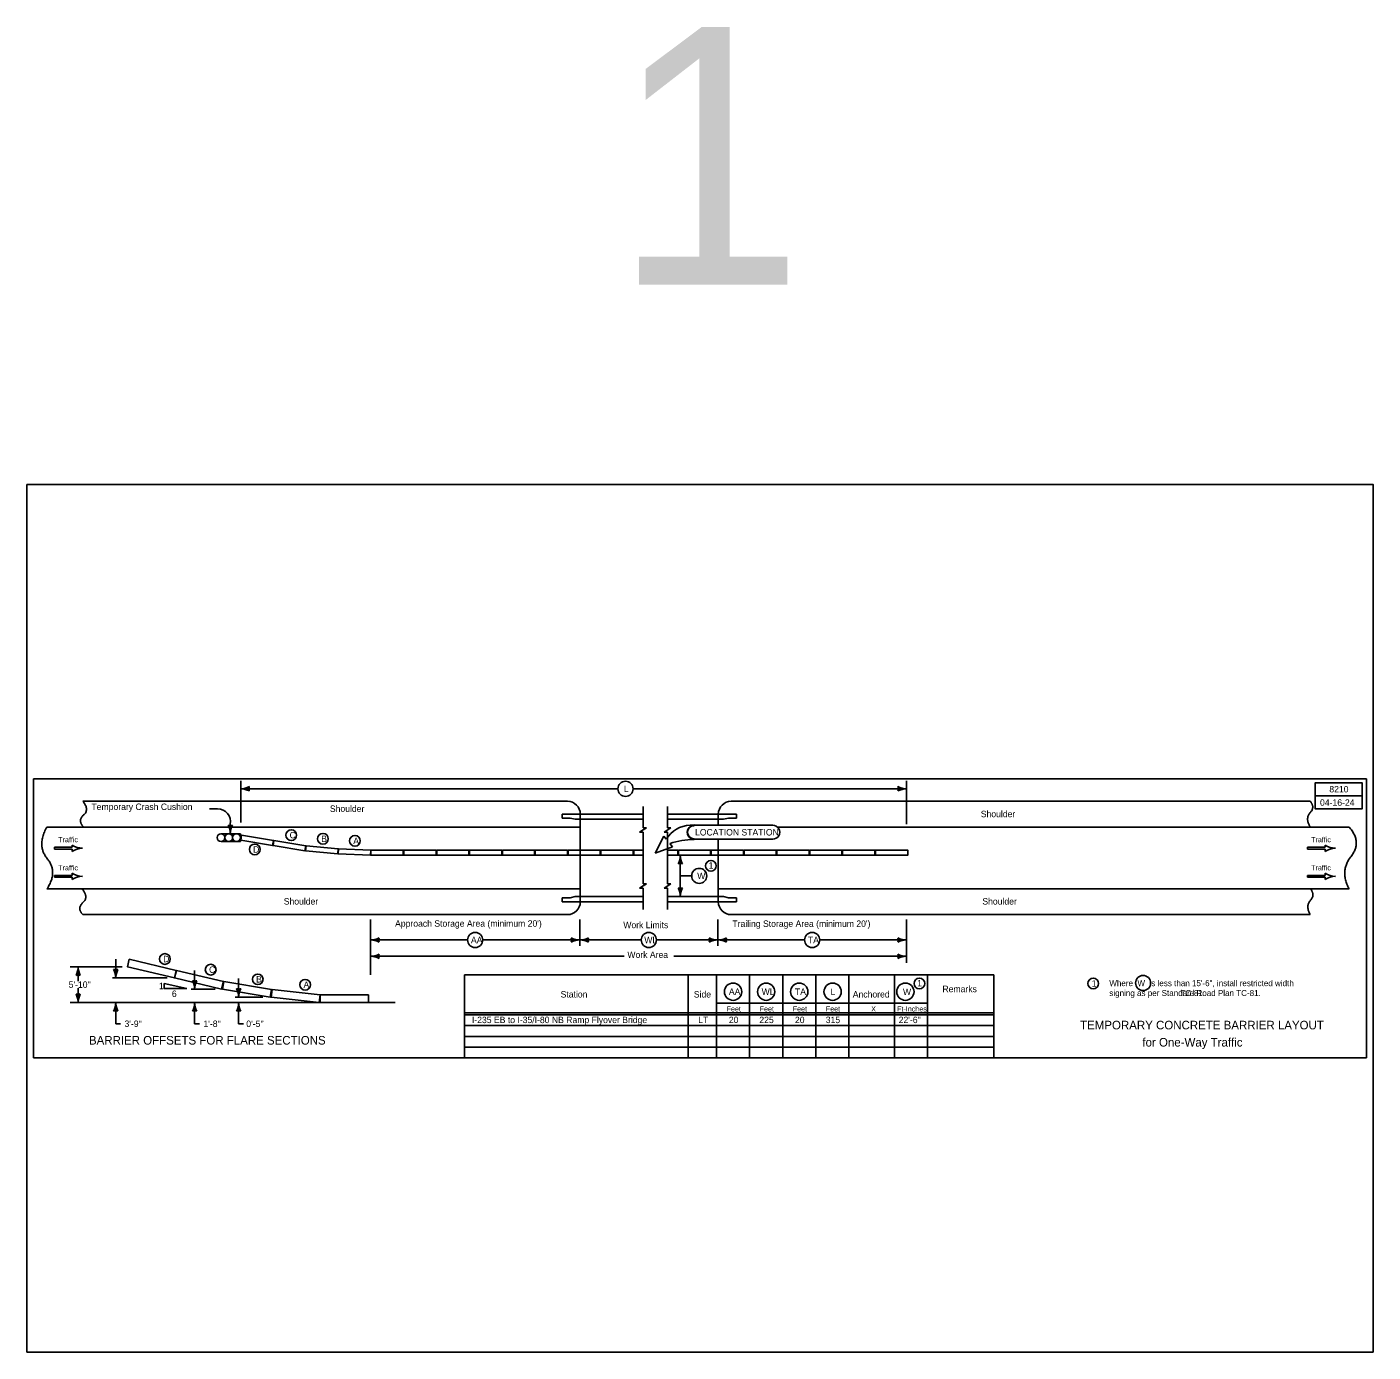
# Model space of a CAD drawing. Extents: x 10133 to 81668, y 7924 to 11018.
# Drawn here: x 10133 to 13268, y 7924 to 11009 of the extents above; entities that cross this region are included whole.
import ezdxf

# ---------------------------------------------------------------- set-up
doc = ezdxf.new("R2010")
doc.units = 0
for name, color, linetype in [('dsnCellsNorthArrow', 7, 'Continuous'), ('DsnShtRevisedText', 7, 'Continuous'), ('dsnTextTabulation', 7, 'Continuous'), ('Level 12', 7, 'Continuous'), ('Level 6', 7, 'Continuous'), ('Level 7', 7, 'Continuous'), ('Level 8', 7, 'Continuous'), ('SheetAddendum', 7, 'Continuous'), ('SheetBorder', 7, 'Continuous'), ('SheetText', 7, 'Continuous'), ('ShtPlotIdentification', 7, 'Continuous')]:
    doc.layers.add(name, color=color, linetype=linetype)

msp = doc.modelspace()

# ---------------------------------------------------------------- linework, layer by layer
at = {"layer": 'dsnCellsNorthArrow'}
for p, q in [((10505.1, 8770.1), (10452.5, 8782.5)), ((10452.5, 8782.5), (10452.5, 8770.1)), ((10452.5, 8770.1), (10505.1, 8770.1))]:
    msp.add_line(p, q, dxfattribs=at)
at = {"layer": 'DsnShtRevisedText'}
msp.add_line((10147.5, 9259), (10147.5, 9259), dxfattribs=at)
at = {"layer": 'dsnTextTabulation'}
for p, q in [((10630.5, 9254.1), (10630.5, 9156.6)), ((12181, 9254.1), (12181, 9153.2)), ((10630.5, 9235.4), (11509, 9235.4)), ((11544.3, 9235.4), (12181, 9235.4)), ((10262.8, 9206.4), (11391.3, 9206.4)), ((10576.7, 9188.7), (10557.9, 9188.7)), ((11567.3, 9194.4), (11567.3, 9144.6)), ((11624.4, 9194.4), (11624.4, 9144.6)), ((11772.7, 9206.4), (13121.1, 9206.4)), ((11421.3, 9176.4), (11379.3, 9176.4)), ((11379.3, 9176.4), (11379.3, 9167.4)), ((11379.3, 9167.4), (11397.3, 9167.4)), ((11409.3, 9164.4), (11397.3, 9167.4)), ((11421.3, 9164.4), (11409.3, 9164.4)), ((11421.3, 9176.4), (11421.3, 8972.4)), ((11421.3, 9176.4), (11567.3, 9176.4)), ((11421.3, 9164.4), (11567.3, 9164.4)), ((11624.4, 9176.4), (11742.7, 9176.4)), ((11624.4, 9164.4), (11742.7, 9164.4)), ((11742.7, 9176.4), (11784.7, 9176.4)), ((11742.7, 9176.4), (11742.7, 9150.5)), ((11742.7, 9164.4), (11754.7, 9164.4)), ((11754.7, 9164.4), (11766.7, 9167.4)), ((11784.7, 9167.4), (11766.7, 9167.4)), ((11784.7, 9176.4), (11784.7, 9167.4)), ((10179.2, 9146.4), (11421.3, 9146.4)), ((10584.6, 9130.9), (10629.6, 9130.9)), ((10606.2, 9153.4), (10606.2, 9130.9)), ((10629.6, 9130.9), (10629.6, 9112.8)), ((11559.3, 9134.5), (11567.3, 9139.5)), ((11559.3, 9134.5), (11567.3, 9134.5)), ((11567.3, 9139.5), (11575.3, 9144.6)), ((11575.3, 9144.6), (11567.3, 9144.6)), ((11567.3, 9134.5), (11567.3, 9074.4)), ((11595.8, 9085.5), (11615.9, 9125.5)), ((11615.9, 9125.5), (11621.6, 9118.4)), ((11616.4, 9134.5), (11632.4, 9144.6)), ((11616.4, 9134.5), (11624.4, 9134.5)), ((11632.4, 9144.6), (11624.4, 9144.6)), ((11624.4, 9134.5), (11624.4, 9074.4)), ((11676.8, 9151), (11686.3, 9151.4)), ((11686.3, 9151.4), (11686.3, 9149.6)), ((11686.3, 9150.5), (11869.4, 9150.5)), ((11880.2, 9146.4), (13211.5, 9146.4)), ((10238.1, 9099.3), (10196.8, 9099.3)), ((10196.8, 9099.3), (10196.8, 9094.8)), ((10196.8, 9094.8), (10238.1, 9094.8)), ((10238.1, 9104.5), (10238.1, 9099.3)), ((10238.1, 9094.8), (10238.1, 9089.5)), ((10262, 9097), (10262, 9097)), ((10629.6, 9112.8), (10584.6, 9112.8)), ((10628.4, 9118.6), (10629.7, 9118.3)), ((10630.1, 9114.9), (10630.1, 9114.9)), ((11636, 9100.5), (11595.8, 9085.5)), ((11630.1, 9107.8), (11636, 9100.5)), ((11686.3, 9118.9), (11686.3, 9117.1)), ((11686.3, 9118), (11869.4, 9118)), ((11742.7, 9118), (11742.7, 8972.4)), ((13155.8, 9099.3), (13114.6, 9099.3)), ((13114.6, 9099.3), (13114.6, 9094.8)), ((13114.6, 9094.8), (13155.8, 9094.8)), ((13155.8, 9104.5), (13155.8, 9099.3)), ((13155.8, 9094.8), (13155.8, 9089.5)), ((13179.8, 9097), (13179.8, 9097)), ((11567.3, 9074.4), (11567.3, 9014.4)), ((11624.4, 9074.4), (11624.4, 9014.4)), ((11654, 9080.7), (11654, 8984.4)), ((10238.1, 9033.8), (10196.8, 9033.8)), ((10196.8, 9033.8), (10196.8, 9029.3)), ((10196.8, 9029.3), (10238.1, 9029.3)), ((10238.1, 9039.1), (10238.1, 9033.8)), ((10238.1, 9029.3), (10238.1, 9024.1)), ((10262, 9031.6), (10262, 9031.6)), ((11680.6, 9032.6), (11654, 9032.6)), ((13155.8, 9033.8), (13114.6, 9033.8)), ((13114.6, 9033.8), (13114.6, 9029.3)), ((13114.6, 9029.3), (13155.8, 9029.3)), ((13155.8, 9039.1), (13155.8, 9033.8)), ((13155.8, 9029.3), (13155.8, 9024.1)), ((13179.8, 9031.6), (13179.8, 9031.6)), ((10179.2, 9002.4), (11421.3, 9002.4)), ((11559.3, 9004.3), (11567.3, 9009.3)), ((11559.3, 9004.3), (11567.3, 9004.3)), ((11567.3, 9009.3), (11575.3, 9014.4)), ((11575.3, 9014.4), (11567.3, 9014.4)), ((11567.3, 9004.3), (11567.3, 8954.4)), ((11616.4, 9004.3), (11632.4, 9014.4)), ((11616.4, 9004.3), (11624.4, 9004.3)), ((11632.4, 9014.4), (11624.4, 9014.4)), ((11624.4, 9004.3), (11624.4, 8954.4)), ((11742.7, 9002.4), (13211.5, 9002.4)), ((11379.3, 8981.4), (11397.3, 8981.4)), ((11379.3, 8972.4), (11379.3, 8981.4)), ((11421.3, 8972.4), (11379.3, 8972.4)), ((11409.3, 8984.4), (11397.3, 8981.4)), ((11421.3, 8984.4), (11409.3, 8984.4)), ((11421.3, 8984.4), (11567.3, 8984.4)), ((11421.3, 8972.4), (11567.3, 8972.4)), ((11624.4, 8984.4), (11742.7, 8984.4)), ((11624.4, 8972.4), (11742.7, 8972.4)), ((11742.7, 8984.4), (11754.7, 8984.4)), ((11742.7, 8972.4), (11784.7, 8972.4)), ((11754.7, 8984.4), (11766.7, 8981.4)), ((11784.7, 8981.4), (11766.7, 8981.4)), ((11784.7, 8972.4), (11784.7, 8981.4)), ((10262.8, 8942.4), (11391.3, 8942.4)), ((11772.7, 8942.4), (13121.1, 8942.4)), ((10932.6, 8931.2), (10932.6, 8802)), ((11420.1, 8931.2), (11420.1, 8869.9)), ((11741.5, 8931.2), (11741.5, 8869.9)), ((12181, 8931.2), (12181, 8830.3)), ((10932.6, 8883.4), (11158.7, 8883.4)), ((11194, 8883.4), (11420.1, 8883.4)), ((11420.1, 8883.4), (11563.3, 8883.4)), ((11598.3, 8883.4), (11741.5, 8883.4)), ((11611, 8883.4), (11741.5, 8883.4)), ((11741.5, 8883.4), (11943.6, 8883.4)), ((11978.9, 8883.4), (12181, 8883.4)), ((10932.6, 8845.5), (11523.4, 8845.5)), ((11638.7, 8845.5), (12181, 8845.5)), ((11640.1, 8845.5), (11741.5, 8845.5)), ((10354.1, 8821), (10232.9, 8821)), ((10251.9, 8821), (10251.9, 8787.5)), ((10339.5, 8838.5), (10339.5, 8795)), ((10523.1, 8812.1), (10523.1, 8768.6)), ((10459, 8795), (10331.8, 8795)), ((10625.5, 8793.5), (10625.5, 8750.1)), ((11672.6, 8609), (11672.6, 8802)), ((11738.6, 8609), (11738.6, 8802)), ((11815.6, 8609), (11815.6, 8802)), ((11892.6, 8609), (11892.6, 8802)), ((11969.6, 8609), (11969.6, 8802)), ((10251.9, 8771.2), (10251.9, 8737.7)), ((10570.9, 8768.6), (10515.3, 8768.6)), ((10681.8, 8750.1), (10617.7, 8750.1)), ((10990.3, 8737.7), (10232.9, 8737.7)), ((10339.5, 8737.7), (10339.5, 8688.4)), ((10523.1, 8737.7), (10523.1, 8688.4)), ((10625.5, 8737.7), (10625.5, 8710.8)), ((11738.6, 8736.2), (12230.1, 8736.2)), ((10339.5, 8688.4), (10350.7, 8688.4)), ((10523.1, 8688.4), (10534.2, 8688.4)), ((10625.5, 8710.8), (10625.5, 8688.4)), ((10625.5, 8688.4), (10636.6, 8688.4)), ((11151.2, 8714), (12384.1, 8714)), ((11151.2, 8709), (12384.1, 8709))]:
    msp.add_line(p, q, dxfattribs=at)
for points in [[(10706.4, 9115.3), (10632.4, 9127.4), (10630.5, 9115.6), (10704.5, 9103.4)], [(10781.9, 9102.9), (10707.9, 9115), (10705.9, 9103.2), (10780, 9091)], [(10857.3, 9095.7), (10782.6, 9102.8), (10781.5, 9090.8), (10856.2, 9083.7)], [(10933.1, 9092.7), (10858.1, 9095.7), (10857.7, 9083.7), (10932.6, 9080.7)], [(10933.8, 9092.7), (11008.8, 9092.7), (11008.8, 9080.7), (10933.8, 9080.7)], [(11010.3, 9092.7), (11085.3, 9092.7), (11085.3, 9080.7), (11010.3, 9080.7)], [(11086.8, 9092.7), (11161.8, 9092.7), (11161.8, 9080.7), (11086.8, 9080.7)], [(11163.3, 9092.7), (11238.3, 9092.7), (11238.3, 9080.7), (11163.3, 9080.7)], [(11239.8, 9092.7), (11314.8, 9092.7), (11314.8, 9080.7), (11239.8, 9080.7)], [(11316.3, 9092.7), (11391.3, 9092.7), (11391.3, 9080.7), (11316.3, 9080.7)], [(11392.8, 9092.7), (11467.8, 9092.7), (11467.8, 9080.7), (11392.8, 9080.7)], [(11469.3, 9092.7), (11544.3, 9092.7), (11544.3, 9080.7), (11469.3, 9080.7)], [(11649.7, 9092.7), (11724.7, 9092.7), (11724.7, 9080.7), (11649.7, 9080.7)], [(11726.2, 9092.7), (11801.2, 9092.7), (11801.2, 9080.7), (11726.2, 9080.7)], [(11802.7, 9092.7), (11877.7, 9092.7), (11877.7, 9080.7), (11802.7, 9080.7)], [(11879.2, 9092.7), (11954.2, 9092.7), (11954.2, 9080.7), (11879.2, 9080.7)], [(11955.7, 9092.7), (12030.7, 9092.7), (12030.7, 9080.7), (11955.7, 9080.7)], [(12032.2, 9092.7), (12107.2, 9092.7), (12107.2, 9080.7), (12032.2, 9080.7)], [(12108.7, 9092.7), (12183.7, 9092.7), (12183.7, 9080.7), (12108.7, 9080.7)], [(10480.3, 8812.6), (10370.9, 8838.5), (10366.7, 8821), (10476.2, 8795.1)], [(10590.1, 8786.6), (10480.6, 8812.5), (10476.5, 8795), (10586, 8769.1)], [(10702.2, 8767.9), (10591.2, 8786.4), (10588.3, 8768.6), (10699.2, 8750.2)], [(10815.3, 8755.6), (10703.5, 8767.9), (10701.5, 8750.1), (10813.3, 8737.7)], [(10927.8, 8755.7), (10815.3, 8755.7), (10815.3, 8737.7), (10927.8, 8737.7)]]:
    msp.add_lwpolyline(points, close=True, dxfattribs=at)
for points in [[(11567.3, 9080.7), (11545.8, 9080.7), (11545.8, 9092.7), (11567.3, 9092.7)], [(11567.3, 9092.7), (11567.3, 9080.7)], [(11624.4, 9080.7), (11624.4, 9092.7)], [(11624.4, 9092.7), (11648.2, 9092.7), (11648.2, 9080.7), (11624.4, 9080.7)]]:
    msp.add_lwpolyline(points, dxfattribs=at)
for centre, radius in [((11526.6, 9235.4), 17.6), ((10584.6, 9121.8), 9), ((10584.6, 9121.8), 9), ((10602.6, 9121.8), 9), ((10602.6, 9121.8), 9), ((10620.6, 9121.8), 9), ((10620.6, 9121.8), 9), ((10748.1, 9127.5), 12.5), ((10821.9, 9119.1), 12.5), ((10896.4, 9114.2), 12.5), ((10663.2, 9094.3), 12.5), ((11725.4, 9056), 12.5), ((11698.3, 9032.6), 17.6), ((11176.4, 8883.4), 17.6), ((11580.8, 8883.4), 17.6), ((11961.2, 8883.4), 17.6), ((10453.8, 8839.2), 12.5), ((10560.5, 8814.3), 12.5), ((10670.2, 8791.9), 12.2), ((10780.5, 8779.2), 12.5), ((11777.1, 8763), 20.1), ((11854.1, 8763), 20.1), ((11931.1, 8763), 20.1), ((12008.9, 8763), 20.1), ((12178.3, 8763), 20.1), ((12211, 8782.2), 12.5), ((12615.8, 8782.2), 12.5), ((12731.9, 8783.3), 17.6)]:
    msp.add_circle(centre, radius, dxfattribs=at)
for centre, radius, start, end in [((10630.5, 9277.9), 42.5, 270, 298.0725), ((10630.5, 9192.9), 42.5, 61.9275, 90), ((10666.1, 9235.4), 16.4, 162.2666, 197.7334), ((12145.4, 9235.4), 16.4, 342.2666, 17.7333), ((12181, 9277.9), 42.5, 241.9275, 270), ((12181, 9192.9), 42.5, 90, 118.0725), ((10576.7, 9158.7), 30, 349.6463, 90), ((11391.3, 9176.4), 30, 0, 90), ((11772.7, 9176.4), 30, 90, 180), ((10606.2, 9166.5), 16.4, 252.2666, 287.7333), ((10563.7, 9130.9), 42.5, 360, 28.0725), ((10648.7, 9130.9), 42.5, 151.9275, 180), ((10264, 9145.3), 48.4, 237.618, 267.648), ((10264, 9048.7), 48.4, 92.352, 122.382), ((13181.7, 9145.3), 48.4, 237.618, 267.648), ((13181.7, 9048.7), 48.4, 92.352, 122.382), ((11611.5, 9080.7), 42.5, 331.9275, 0), ((11654, 9045.1), 16.4, 72.2666, 107.7334), ((11696.5, 9080.7), 42.5, 180, 208.0725), ((10264, 9079.9), 48.4, 237.618, 267.648), ((10264, 8983.3), 48.4, 92.352, 122.382), ((13181.7, 9079.9), 48.4, 237.618, 267.648), ((13181.7, 8983.3), 48.4, 92.352, 122.382), ((11654, 9020.1), 16.4, 252.2666, 287.7334), ((11611.5, 8984.4), 42.5, 0, 28.0725), ((11696.5, 8984.4), 42.5, 151.9275, 180), ((11391.3, 8972.4), 30, 270, 360), ((11772.7, 8972.4), 30, 180, 270), ((10932.6, 8925.9), 42.5, 270, 298.0725), ((10932.6, 8840.9), 42.5, 61.9275, 90), ((10968.2, 8883.4), 16.4, 162.2666, 197.7334), ((11384.5, 8883.4), 16.4, 342.2666, 17.7333), ((11420.1, 8925.9), 42.5, 241.9275, 270), ((11420.1, 8840.9), 42.5, 90, 118.0725), ((11420.1, 8925.9), 42.5, 270, 298.0725), ((11420.1, 8840.9), 42.5, 61.9275, 90), ((11455.7, 8883.4), 16.4, 162.2666, 197.7334), ((11705.9, 8883.4), 16.4, 342.2666, 17.7333), ((11741.5, 8925.9), 42.5, 241.9275, 270), ((11741.5, 8840.9), 42.5, 90, 118.0725), ((11741.5, 8925.9), 42.5, 270, 298.0725), ((11741.5, 8840.9), 42.5, 61.9275, 90), ((11777.1, 8883.4), 16.4, 162.2666, 197.7334), ((12145.4, 8883.4), 16.4, 342.2666, 17.7333), ((12181, 8925.9), 42.5, 241.9275, 270), ((12181, 8840.9), 42.5, 90, 118.0725), ((10932.6, 8888), 42.5, 270, 298.0725), ((10932.6, 8803), 42.5, 61.9275, 90), ((10968.2, 8845.5), 16.4, 162.2666, 197.7334), ((12145.4, 8845.5), 16.4, 342.2666, 17.7333), ((12181, 8888), 42.5, 241.9275, 270), ((12181, 8803), 42.5, 90, 118.0725), ((10209.4, 8821), 42.5, 331.9275, 0), ((10294.4, 8821), 42.5, 180, 208.0725), ((10339.5, 8830.7), 16.4, 252.2666, 287.7334), ((10297, 8795), 42.5, 0, 28.0725), ((10382, 8795), 42.5, 151.9275, 180), ((10251.9, 8785.4), 16.4, 72.2666, 107.7334), ((10523.1, 8804.3), 16.4, 252.2666, 287.7334), ((10480.6, 8768.6), 42.5, 0, 28.0725), ((10565.6, 8768.6), 42.5, 151.9275, 180), ((10251.9, 8773.4), 16.4, 252.2666, 287.7334), ((10209.4, 8737.7), 42.5, 0, 28.0725), ((10294.4, 8737.7), 42.5, 151.9275, 180), ((10625.5, 8785.7), 16.4, 252.2666, 287.7334), ((10583, 8750.1), 42.5, 0, 28.0725), ((10668, 8750.1), 42.5, 151.9275, 180), ((10297, 8737.7), 42.5, 331.9275, 0), ((10339.5, 8702.1), 16.4, 72.2666, 107.7334), ((10382, 8737.7), 42.5, 180, 208.0725), ((10480.6, 8737.7), 42.5, 331.9275, 0), ((10523.1, 8702.1), 16.4, 72.2666, 107.7334), ((10565.6, 8737.7), 42.5, 180, 208.0725), ((10583, 8737.7), 42.5, 331.9275, 0), ((10625.5, 8702.1), 16.4, 72.2666, 107.7334), ((10668, 8737.7), 42.5, 180, 208.0725)]:
    msp.add_arc(centre, radius, start, end, dxfattribs=at)
for centre, major_axis, start_param, end_param in [((11681.3, 9080.7), (-70.8, 0), 4.776871, 5.71778), ((11686.3, 9134.2), (-16.3, 0), 4.712389, 7.853982), ((11686.3, 9134.2), (15.4, 0), 1.570796, 4.712389), ((11869.4, 9134.2), (16.3, 0), 4.712389, 7.853982), ((11683.5, 8961), (-156.9, 0), 4.694293, 5.059134)]:
    msp.add_ellipse(centre, major_axis=major_axis, ratio=0.995025, start_param=start_param, end_param=end_param, dxfattribs=at)
for points in [[(10262.8, 9206.4), (10278.9, 9187.1), (10250, 9161.5), (10264.4, 9146.5)], [(13121.1, 9206.4), (13132.9, 9192.3), (13109.3, 9167.3), (13120.7, 9146.5)], [(10179.2, 9146.4), (10154.6, 9103.8), (10205.3, 9041.6), (10179.2, 9002.4)], [(13211.5, 9146.4), (13242.9, 9112), (13189.5, 9044), (13211.5, 9002.4)], [(10261.2, 9002.4), (10277.3, 8983.1), (10248.4, 8957.5), (10262.8, 8942.4)], [(13121.6, 9002.4), (13133.4, 8988.3), (13109.8, 8963.3), (13121.1, 8942.4)]]:
    msp.add_open_spline(points, degree=2, dxfattribs=at)
at = {"layer": 'Level 12'}
for p, q in [((11151.2, 8802), (11151.2, 8609)), ((11151.2, 8802), (12384.1, 8802)), ((12046.6, 8609), (12046.6, 8802)), ((12153.1, 8609), (12153.1, 8802)), ((12230.1, 8609), (12230.1, 8802)), ((12384.1, 8609), (12384.1, 8802))]:
    msp.add_line(p, q, dxfattribs=at)
at = {"layer": 'Level 8'}
for p, q in [((10147.5, 9259), (13252.5, 9259)), ((10147.5, 8609), (10147.5, 9259)), ((13252.5, 9259), (13252.5, 8609)), ((10147.5, 8609), (13252.5, 8609))]:
    msp.add_line(p, q, dxfattribs=at)
msp.add_lwpolyline([(13242.5, 9249), (13242.5, 9189), (13132.5, 9189), (13132.5, 9249), (13242.5, 9249), (13242.5, 9219), (13132.5, 9219)], dxfattribs=at)
at = {"layer": 'SheetAddendum'}
msp.add_line((13252.5, 8609), (10147.5, 8609), dxfattribs=at)
at = {"layer": 'SheetBorder'}
msp.add_lwpolyline([(10132.5, 9944), (13267.5, 9944), (13267.5, 7924), (10132.5, 7924)], close=True, dxfattribs=at)
at = {"layer": 'ShtPlotIdentification'}
for p, q in [((11151.2, 8684), (12384.1, 8684)), ((11151.2, 8659), (12384.1, 8659)), ((11151.2, 8634), (12384.1, 8634)), ((11151.2, 8609), (12384.1, 8609))]:
    msp.add_line(p, q, dxfattribs=at)

# ---------------------------------------------------------------- texts
at = {"layer": 'dsnCellsNorthArrow'}
for s, height, p in [('L', 15, (11522.7, 9227.9)), ('Temporary Crash Cushion', 15, (10282.8, 9186.1)), ('Shoulder', 15, (10838.1, 9181.6)), ('Shoulder', 15, (12353.9, 9169.3)), ('Traffic', 12, (10205.5, 9111)), ('C', 15, (10744.2, 9120)), ('B', 15, (10817.9, 9111.6)), ('LOCATION STATION', 15, (11688.5, 9126.7)), ('Traffic', 12, (13123.3, 9111)), ('D', 15, (10659.3, 9086.8)), ('A', 15, (10892.5, 9106.7)), ('1', 15, (11720.1, 9049.5)), ('Traffic', 12, (10205.5, 9045.6)), ('W', 15, (11693.6, 9025.1)), ('Traffic', 12, (13123.3, 9045.6)), ('Shoulder', 15, (10730.6, 8965.9)), ('Shoulder', 15, (12357.6, 8965.9)), ("Approach Storage Area (minimum 20')", 15, (10989.9, 8914.3)), ('Work Limits', 15, (11521.4, 8910.9)), ("Trailing Storage Area (minimum 20')", 15, (11775.4, 8913.9)), ('AA', 15, (11166.6, 8875.9)), ('WL', 15, (11570.3, 8875.9)), ('TA', 15, (11951.4, 8875.9)), ('D', 15, (10449.9, 8831.7)), ('Work Area', 15, (11530.9, 8841.6)), ('C', 15, (10556.6, 8806.8)), ("5'-10''", 15, (10229.7, 8772)), ('1', 15, (10439.9, 8768.9)), ('B', 15, (10666.3, 8784.4)), ('A', 15, (10776.6, 8771.7)), ('1', 15, (12205.8, 8775.6)), ('1', 15, (12612.4, 8774.7)), ('Where  W  is less than 15\'-6", install restricted width', 14, (12653.3, 8775.9)), ('6', 15, (10470.1, 8750.8)), ('Station', 15, (11375.4, 8749.5)), ('Side', 15, (11685.6, 8749.5)), ('AA', 15, (11767.3, 8755.5)), ('WL', 15, (11843.6, 8755.5)), ('TA', 15, (11921.2, 8755.5)), ('L', 15, (12004, 8755.1)), ('Anchored', 15, (12055.8, 8749.5)), ('W', 15, (12172.7, 8755.1)), ('Remarks', 15, (12264.6, 8761.9)), ('signing as per Standard Road Plan TC-81.', 14, (12653.3, 8752.9)), ('                                TC-81', 14, (12652.6, 8752.9)), ('Feet', 12, (11762.1, 8717)), ('Feet', 12, (11839.1, 8717)), ('Feet', 12, (11916.1, 8717)), ('Feet', 12, (11993.1, 8717)), ('X', 12, (12098.7, 8717)), ('Ft-Inches', 12, (12159.1, 8717)), ("3'-9''", 15, (10359.8, 8680.9)), ("1'-8''", 15, (10543.7, 8680.9)), ("0'-5''", 15, (10643.4, 8680.9)), ('I-235 EB to I-35/I-80 NB Ramp Flyover Bridge', 15, (11168.9, 8689.9)), ('LT', 15, (11695.8, 8689.9)), ('20', 15, (11767.2, 8689.9)), ('225', 15, (11838.2, 8689.9)), ('20', 15, (11921.2, 8689.9)), ('315', 15, (11992.9, 8689.9)), ('22\'-6"', 15, (12162.8, 8689.9))]:
    msp.add_text(s, height=height, dxfattribs=at).set_placement(p)
at = {"layer": 'Level 6'}
for s, p in [('8210', (13165.7, 9227)), ('04-16-24', (13144, 9196))]:
    msp.add_text(s, height=15, dxfattribs=at).set_placement(p)
at = {"layer": 'Level 7'}
for s, p in [('TEMPORARY CONCRETE BARRIER LAYOUT', (12585.2, 8675.3)), ('BARRIER OFFSETS FOR FLARE SECTIONS', (10277, 8639.9)), ('for One-Way Traffic', (12730.3, 8635.3))]:
    msp.add_text(s, height=20, dxfattribs=at).set_placement(p)
at = {"layer": 'SheetText'}
msp.add_text('1', height=600, dxfattribs=at).set_placement((11496.6, 10409.2))

doc.saveas('drawing.dxf')
